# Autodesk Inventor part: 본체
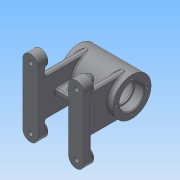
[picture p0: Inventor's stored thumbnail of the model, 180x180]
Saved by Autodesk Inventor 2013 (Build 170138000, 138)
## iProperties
Created: 2015-11
Part Number: 본체
Material: 일반
Document SubType Name: Modeling
Designer: Administrator
Density: 1 g/cm^3
Author: Administrator
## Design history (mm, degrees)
sketch "스케치1"
  geometry: L1 (-35, 25)-(0, 25); L2 (0, 25)-(0, 0); L3 (0, 0)-(-35, 0); L4 (-35, 0)-(-35, 25); L5 (-35, 16)-(-23, 16); L6 (-23, 16)-(-23, 14); L7 (-23, 14)-(-21, 14); L8 (-21, 14)-(-21, 21); L9 (-21, 21)-(0, 21); 1 further point
  constraints: 18 end point, 4 parallel, 4 perpendicular, 2 point on line, 1 coincident, 1 horizontal
  dimensions: "d0" = 35 distance of L2.end L3.end; "d1" = 25 distance of L1.end L2.end; "d2" = 32 diameter of L5 L3; "d3" = 28 diameter of L7 L3; "d4" = 42 diameter of L9 L3; "d5" = 2 distance between parallel lines of L6 L8; "d6" = 12 distance of L5.start L5.end
revolve "회전1" sketch "스케치1" stored, may be unused: angle "d7" = 90 deg
fillet "모깎기1" dims "d8" = 0.3
fillet "모깎기2" dims "d9" = 3
chamfer "모따기1" distance "d10" = 1; stored, may be unused: second distance "d11" = 2, angle "d12" = 45 deg
sketch "스케치2"
  geometry: C1 r 25 at (0, 0) reference; 1 further point
  constraints: 1 vertical alignment
  dimensions: "d13" = 20 distance of C1.centre point (0, 20)
hole "구멍1" sketch "스케치2" at (0, 20) diameter "d14" = 3.242; stored, may be unused: countersink angle "d18" = 90 deg, drill point angle "d20" = 118 deg; dims "d15" = 8, "d16" = 4, "d17" = 2, "d19" = 10
node "작업 평면1"
sketch "스케치3"
  geometry: C1 r 5 at (0, 0); 1 further point
  constraints: 1 centre point, 1 coincident
  dimensions: "d25" = 10 diameter of C1
extrude "돌출1" join sketch "스케치3" stored distance "d26" = 10 (= d25); taper "d27" = 0 deg
hole "구멍2" diameter "d30" = 5.188; stored, may be unused: countersink angle "d34" = 90 deg, drill point angle "d36" = 118 deg; dims "d31" = 28, "d32" = 4, "d33" = 2, "d35" = 28, "d75" = 10, "d76" = 10
sketch "스케치4"
  geometry: L1 (0, 0)-(-24.249, 14); L2 (0, 0)-(28, 0)
  constraints: 4 end point, 1 equal length, 1 horizontal
  dimensions: "d37" = 28 distance of L1.start L1.end; "d38" = 150 deg angle of L2 L1
node "작업 평면2"
sketch "스케치5"
  geometry: C1 r 6 at (0, 0); 1 further point
  constraints: 1 centre point, 1 coincident
  dimensions: "d39" = 12 diameter of C1
extrude "돌출2" join sketch "스케치5" stored distance "d40" = 10; taper "d41" = 0 deg
hole "구멍3" diameter "d44" = 5.188; stored, may be unused: countersink angle "d48" = 90 deg, drill point angle "d50" = 118 deg; dims "d45" = 28, "d46" = 4, "d47" = 2, "d49" = 28, "d77" = 10, "d78" = 10
node "작업 평면3"
sketch "스케치7"
  geometry: L1 (58, -50)-(68, -50); L2 (68, -50)-(68, 50); L3 (68, 50)-(58, 50); L4 (58, 50)-(58, -50); 2 further points
  constraints: 8 end point, 2 parallel, 1 horizontal, 1 horizontal alignment, 1 midpoint, 1 perpendicular
  dimensions: "d52" = 10 distance of L3.end L2.end; "d53" = 100 distance of L2.end L1.end; "d54" = 68 distance from line of point (0, 0) L2
extrude "돌출3" join sketch "스케치7" distance "d55" = 20; taper "d56" = 0 deg
fillet "모깎기3" dims "d57" = 10
sketch "스케치8"
  geometry: C1 r 10 at (10, 80); C2 r 10 at (10, 0); A1 r 10 centre (10, 80) between (20, 80) and (0, 80) reference; A2 r 10 centre (10, 0) between (0, 0) and (20, 0) reference; 1 further point
  constraints: 2 centre point, 2 coincident
  dimensions: "d58" = 20 diameter of C1; "d59" = 20 diameter of C2
extrude "돌출4" join sketch "스케치8" distance "d60" = 3; taper "d61" = 0 deg
hole "구멍4" diameter "d64" = 6; stored, may be unused: countersink angle "d68" = 90 deg, drill point angle "d70" = 0 deg; dims "d62" = 10, "d63" = 10, "d65" = 28, "d66" = 12, "d67" = 4, "d69" = 30
fillet "모깎기4" dims "d71" = 0.3
chamfer "모따기2" distance "d72" = 1; stored, may be unused: second distance "d73" = 2, angle "d74" = 45 deg
sketch "스케치9"
  geometry: L1 (20, 80)-(20, 0) reference; L2 (20, 65)-(12, 65); L3 (12, 65)-(12, 15); L4 (12, 15)-(20, 15); L5 (20, 15)-(20, 65); 2 further points
  constraints: 8 end point, 2 midpoint, 2 parallel, 1 horizontal, 1 perpendicular
  dimensions: "d79" = 8 distance of L4.end L3.end; "d80" = 50 distance of L3.end L2.end
extrude "돌출5" join sketch "스케치9" stored distance "d81" = 3; taper "d82" = 0 deg
node "작업 평면4"
sketch "스케치11"
  geometry: L1 (-20, 4)-(20, 4); L2 (20, 4)-(20, -4); L3 (20, -4)-(-20, -4); L4 (-20, -4)-(-20, 4); L5 (-28, 25)-(-20, 25) reference; L6 (-20, 25)-(-20, -25) reference; L7 (-20, -25)-(-28, -25) reference; L8 (-28, -25)-(-28, 25) reference; L9 (20, 25)-(28, 25) reference; L10 (28, 25)-(28, -25) reference; L11 (28, -25)-(20, -25) reference; L12 (20, -25)-(20, 25) reference; 2 further points
  constraints: 8 end point, 2 midpoint, 2 parallel, 1 horizontal, 1 perpendicular
  dimensions: "d84" = 40 distance of L2.end L3.end; "d85" = 8 distance of L1.end L2.end
extrude "돌출6" join sketch "스케치11" stored distance "d86" = 3; taper "d87" = 0 deg
sketch "스케치12"
  geometry: L1 (8.5, 13.5)-(31.5, 13.5); L2 (31.5, 13.5)-(31.5, 6.5); L3 (31.5, 6.5)-(8.5, 6.5); L4 (8.5, 6.5)-(8.5, 13.5); L5 (8.5, 13.5)-(31.5, 6.5); L6 (31.5, 13.5)-(8.5, 6.5); L7 (40, -23)-(60, -23) reference; 2 further points
  constraints: 12 end point, 2 midpoint, 2 parallel, 1 horizontal, 1 perpendicular
  dimensions: "d88" = 23 distance of L2.end L3.end; "d89" = 7 distance of L1.end L2.end; "d90" = 11.5 distance from line of L4 point (20, 45); "d91" = 33 distance from line of L7 point (20, 10)
extrude "돌출7" cut sketch "스케치12" stored distance "d92" = 3; taper "d93" = 0 deg
fillet "모깎기5" dims "d94" = 3.5
node "작업 평면5"
sketch "스케치13"
  geometry: L1 (2.5, -68)-(2.5, -58) reference; L2 (2.5, -58)-(2.5, 0) reference; L3 (2.5, 0)-(-37.5, 0) reference; L4 (-37.5, 0)-(-37.5, -58) reference; L5 (-37.5, -58)-(-37.5, -68) reference; L6 (-37.5, -68)-(-57.5, -68) reference; L7 (-57.5, -68)-(-57.5, -58) reference; L8 (-57.5, -58)-(-45.5, -58) reference; L9 (-45.5, -58)-(-37.5, -58) reference; L10 (22.5, -68)-(2.5, -68) reference; L11 (22.5, -58)-(22.5, -68) reference; L12 (10.5, -58)-(22.5, -58) reference; L13 (2.5, -58)-(10.5, -58) reference; L14 (10.5, 0)-(2.5, 0) reference; L15 (17.5, 0)-(10.5, 0) reference; L16 (-37.5, 0)-(-45.5, 0) reference; L17 (-45.5, 0)-(-52.5, 0) reference; L18 (-45.5, -58)-(-45.5, 0) reference; L19 (10.5, 0)-(10.5, -58) reference; L20 (17.5, 25)-(-52.5, 25) reference; L21 (-52.5, 25)-(-52.5, -25) reference; 2 further points
  constraints: 1 other
  dimensions: "d99" = 25 distance from line of point (-17.5, 0) L20; "d100" = 35 distance from line of point (-17.5, 0) L21
feature "엠보싱1" sketch "스케치13" dims "d11" = 2, "d101" = 0.5, "d102" = 0
fillet "모깎기11" dims "d104" = 2
fillet "모깎기12" dims "d105" = 2
node "솔리드1"
pattern_circular "원형 패턴1" dims angle "d22" = 360 deg
mirror "대칭1"
mirror "대칭2"
mirror "대칭3"
node "절단 모서리 투영3"
node "절단 모서리 투영4"
other parameters: "d24" = 28, "d83" = -45
